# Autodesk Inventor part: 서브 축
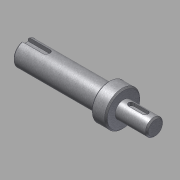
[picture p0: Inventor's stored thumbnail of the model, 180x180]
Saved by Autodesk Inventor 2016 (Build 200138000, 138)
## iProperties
Created: 2014-10
Part Number: 서브 축
Document SubType Name: Modeling
Designer: KYOUNG IL JANG
Density: 1 g/cm^3
Mass: 19.9624 g
Surface Area: 57.7178 cm^2
Volume: 19.9624 cm^3
Material: 강철, 연강
Appearance: 금속-강(스테인리스, 브러시됨)
Author: SeoGD™ [www.esajin.kr]
Revision Number: 1
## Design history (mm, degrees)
sketch "스케치1"
  geometry: L1 (-16.331, 0)-(-108.831, 0); L2 (-16.331, 0)-(-16.331, -6); L3 (-16.331, -6)-(-38.831, -6); L4 (-38.831, -12.5)-(-46.5, -12.5); L5 (-46.5, -8.5)-(-108.831, -8.5); L6 (-108.831, -8.5)-(-108.831, 0); L7 (-46.5, -8.5)-(-46.5, -12.5); L8 (-38.831, -6)-(-38.831, -12.5); L9 (-46.5, 12.249)-(-46.5, -12.249) reference; L10 (-38.831, -17)-(-38.831, 17) reference; 2 further points
  constraints: 17 end point, 4 perpendicular, 2 collinear, 2 parallel, 1 horizontal, 1 midpoint, 1 point on line
  dimensions: "d1" = 12 diameter of L3 L1; "d2" = 25 diameter of L4 L1; "d3" = 17 diameter of L5 L1; "d18" = 22.5 distance of L2.end L3.end; "d20" = 70 distance between parallel lines of L6 L8; "d21" = 7.66872 distance of L4.start L4.end (derived)
revolve "회전1" sketch "스케치1" stored, may be unused: angle "d5" = 90 deg
chamfer "모따기1" distance "d6" = 1; stored, may be unused: second distance "d7" = 2, angle "d8" = 45 deg
node "작업 평면1"
sketch "스케치2"
  geometry: L1 (11.25, 5)-(11.25, -5) reference; L2 (-5.75, -2)-(4.25, -2); L3 (4.25, 2)-(-5.75, 2); A1 r 2 centre (4.25, 0) between (4.25, -2) and (4.25, 2); A2 r 2 centre (-5.75, 0) between (-5.75, 2) and (-5.75, -2); 2 further points
  constraints: 4 end point, 4 point on circle, 4 tangent, 2 centre point, 1 horizontal alignment, 1 midpoint, 1 parallel, 1 perpendicular
  dimensions: "d9" = 4 distance between parallel lines of L2 L3; "d10" = 14 dimension on A1 A2; "d11" = 5 distance edge to line of A1 L1
extrude "돌출1" cut sketch "스케치2" distance "d12" = 2.5; taper "d13" = 0 deg
node "작업 평면2"
sketch "스케치3"
  geometry: L1 (-31.166, -7.5)-(-31.166, 7.5) reference; L2 (-31.166, 2.5)-(-15.666, 2.5); L3 (-15.666, -2.5)-(-31.166, -2.5); A1 r 2.5 centre (-15.666, 0) between (-15.666, -2.5) and (-15.666, 2.5); 2 further points
  constraints: 4 end point, 2 perpendicular, 2 point on circle, 2 point on line, 2 tangent, 1 centre point, 1 horizontal alignment, 1 midpoint
  dimensions: "d14" = 5 distance between parallel lines of L3 L2; "d15" = 18 dimension on A1 L1
extrude "돌출2" cut sketch "스케치3" distance "d16" = 3; taper "d17" = 0 deg
sketch "스케치4"
  geometry: C1 r 12.5 at (0, 0) reference; 1 further point
extrude "돌출3" join sketch "스케치4" distance "d22" = 3; taper "d23" = 0 deg
chamfer "모따기2" distance "d24" = 1; stored, may be unused: second distance "d25" = 2, angle "d26" = 45 deg
node "솔리드1"
node "참조4"
node "참조5"
